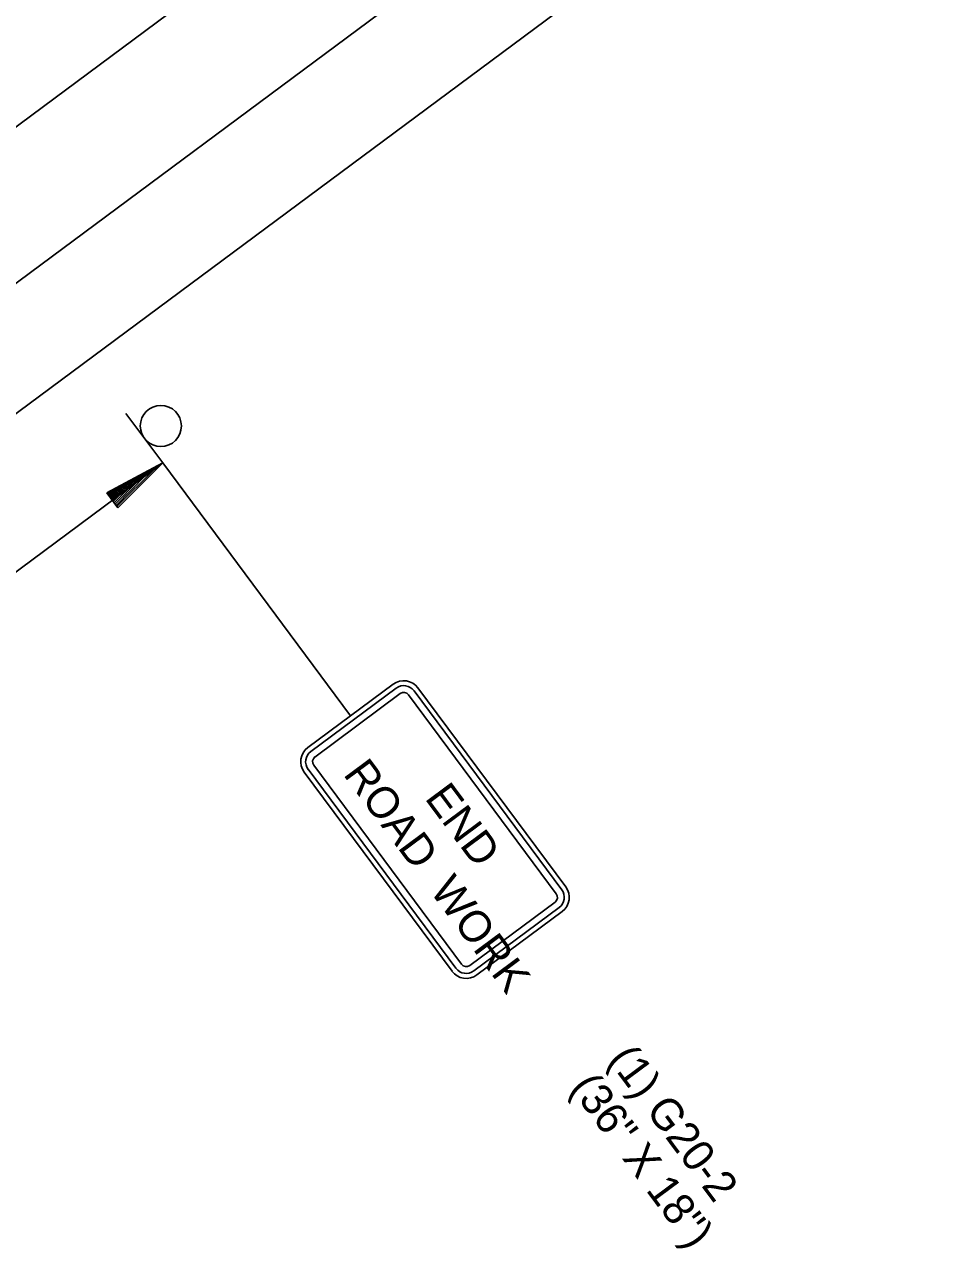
# Model space of a CAD drawing. Extents: x -238 to 1487, y -1123 to 446.
# Drawn here: x 956.7 to 1130, y -467 to -232.3 of the extents above; entities that cross this region are included whole.
import ezdxf

# ---------------------------------------------------------------- set-up
doc = ezdxf.new("R2010")
doc.units = 0
for name, color, linetype in [('P_TC_Signs_Temporary', 7, 'Continuous'), ('R_Border Prem', 7, 'Continuous'), ('R_Draft', 7, 'Continuous'), ('STAMP', 7, 'Continuous')]:
    doc.layers.add(name, color=color, linetype=linetype)

msp = doc.modelspace()

# ---------------------------------------------------------------- linework, layer by layer
at = {"layer": 'P_TC_Signs_Temporary'}
for p, q in [((1027, -358.09), (1010.74, -370.16)), ((1027.56, -358.84), (1011.3, -370.91)), ((1059.89, -396.72), (1031.72, -358.78)), ((1028.34, -359.89), (1012.08, -371.97)), ((1058.08, -398.06), (1029.92, -360.13)), ((1059.14, -397.28), (1030.97, -359.34)), ((1010.04, -374.88), (1038.21, -412.82)), ((1010.8, -374.32), (1038.97, -412.26)), ((1011.85, -373.54), (1040.02, -411.48)), ((1041.59, -411.71), (1057.85, -399.64)), ((1042.38, -412.76), (1058.63, -400.69)), ((1042.93, -413.51), (1059.19, -401.44))]:
    msp.add_line(p, q, dxfattribs=at)
for centre, radius, start, end in [((1029.01, -360.8), 3.38, 36.5953, 126.5953), ((1029.01, -360.8), 2.44, 36.5953, 126.5953), ((1029.01, -360.8), 1.13, 36.5953, 126.5953), ((1012.75, -372.87), 3.38, 126.5953, 216.5953), ((1012.75, -372.87), 2.44, 126.5953, 216.5953), ((1012.75, -372.87), 1.13, 126.5953, 216.5953), ((1057.18, -398.73), 1.13, 306.5953, 36.5953), ((1057.18, -398.73), 2.44, 306.5953, 36.5953), ((1057.18, -398.73), 3.38, 306.5953, 36.5953), ((1040.92, -410.8), 3.38, 216.5953, 306.5953), ((1040.92, -410.8), 2.44, 216.5953, 306.5953), ((1040.92, -410.8), 1.13, 216.5953, 306.5953)]:
    msp.add_arc(centre, radius, start, end, dxfattribs=at)
at = {"layer": 'R_Draft'}
for p, q in [((1263.6, -22.73), (712.73, -431.77)), ((1277.87, -41.95), (727, -450.98)), ((1289.76, -57.96), (738.89, -467)), ((822.5, -435.13), (983.07, -315.9)), ((972.39, -321.59), (983.07, -315.9)), ((974.53, -324.47), (983.07, -315.9)), ((983.06, -315.9), (1018.87, -364.12)), ((972.57, -321.83), (981.47, -317.09)), ((972.75, -322.07), (979.81, -318.31)), ((974.17, -323.99), (979.81, -318.31)), ((974.35, -324.23), (981.47, -317.09)), ((972.93, -322.31), (978.22, -319.5)), ((973.12, -322.57), (976.58, -320.71)), ((973.81, -323.5), (976.58, -320.71)), ((973.99, -323.75), (978.22, -319.5)), ((972.39, -321.59), (974.53, -324.47)), ((973.29, -322.81), (974.98, -321.9)), ((973.63, -323.26), (974.98, -321.9))]:
    msp.add_line(p, q, dxfattribs=at)
at = {"layer": 'STAMP'}
msp.add_line((983.06, -315.9), (976.06, -306.46), dxfattribs=at)
msp.add_circle((982.71, -308.85), 3.92, dxfattribs=at)

# ---------------------------------------------------------------- texts
at = {"layer": 'P_TC_Signs_Temporary'}
for s, p in [('ROAD  WORK', (1017.34, -375.27)), ('END', (1032.88, -379.84))]:
    msp.add_text(s, height=6, rotation=306.5953, dxfattribs=at).set_placement(p)
at = {"layer": 'R_Border Prem'}
for s, p in [('(1) G20-2', (1067.81, -429.7)), ('(36" X 18")', (1060.58, -435.06))]:
    msp.add_text(s, height=6, rotation=306.5953, dxfattribs=at).set_placement(p)

doc.saveas('drawing.dxf')
